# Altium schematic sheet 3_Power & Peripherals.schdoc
size 309 x 223 mm; Symbol: Artery_A4; Device: Artery_A4; Company: Artery Technology; Drawed: SD; Version: 1.0; Page Size: A4; @Project Name: AT-START-F490; @Page Count: 4; @Update Date: 2024-11-26; @Create Date: 2024-11-26; @Schematic Name: AT-START-F490; @Page No: 3; @Page Name: Power & Peripherals; @Board Name: AT-START-F490 V1.0; @Create Time: 14:05:45; @Update Time: 14:06:00
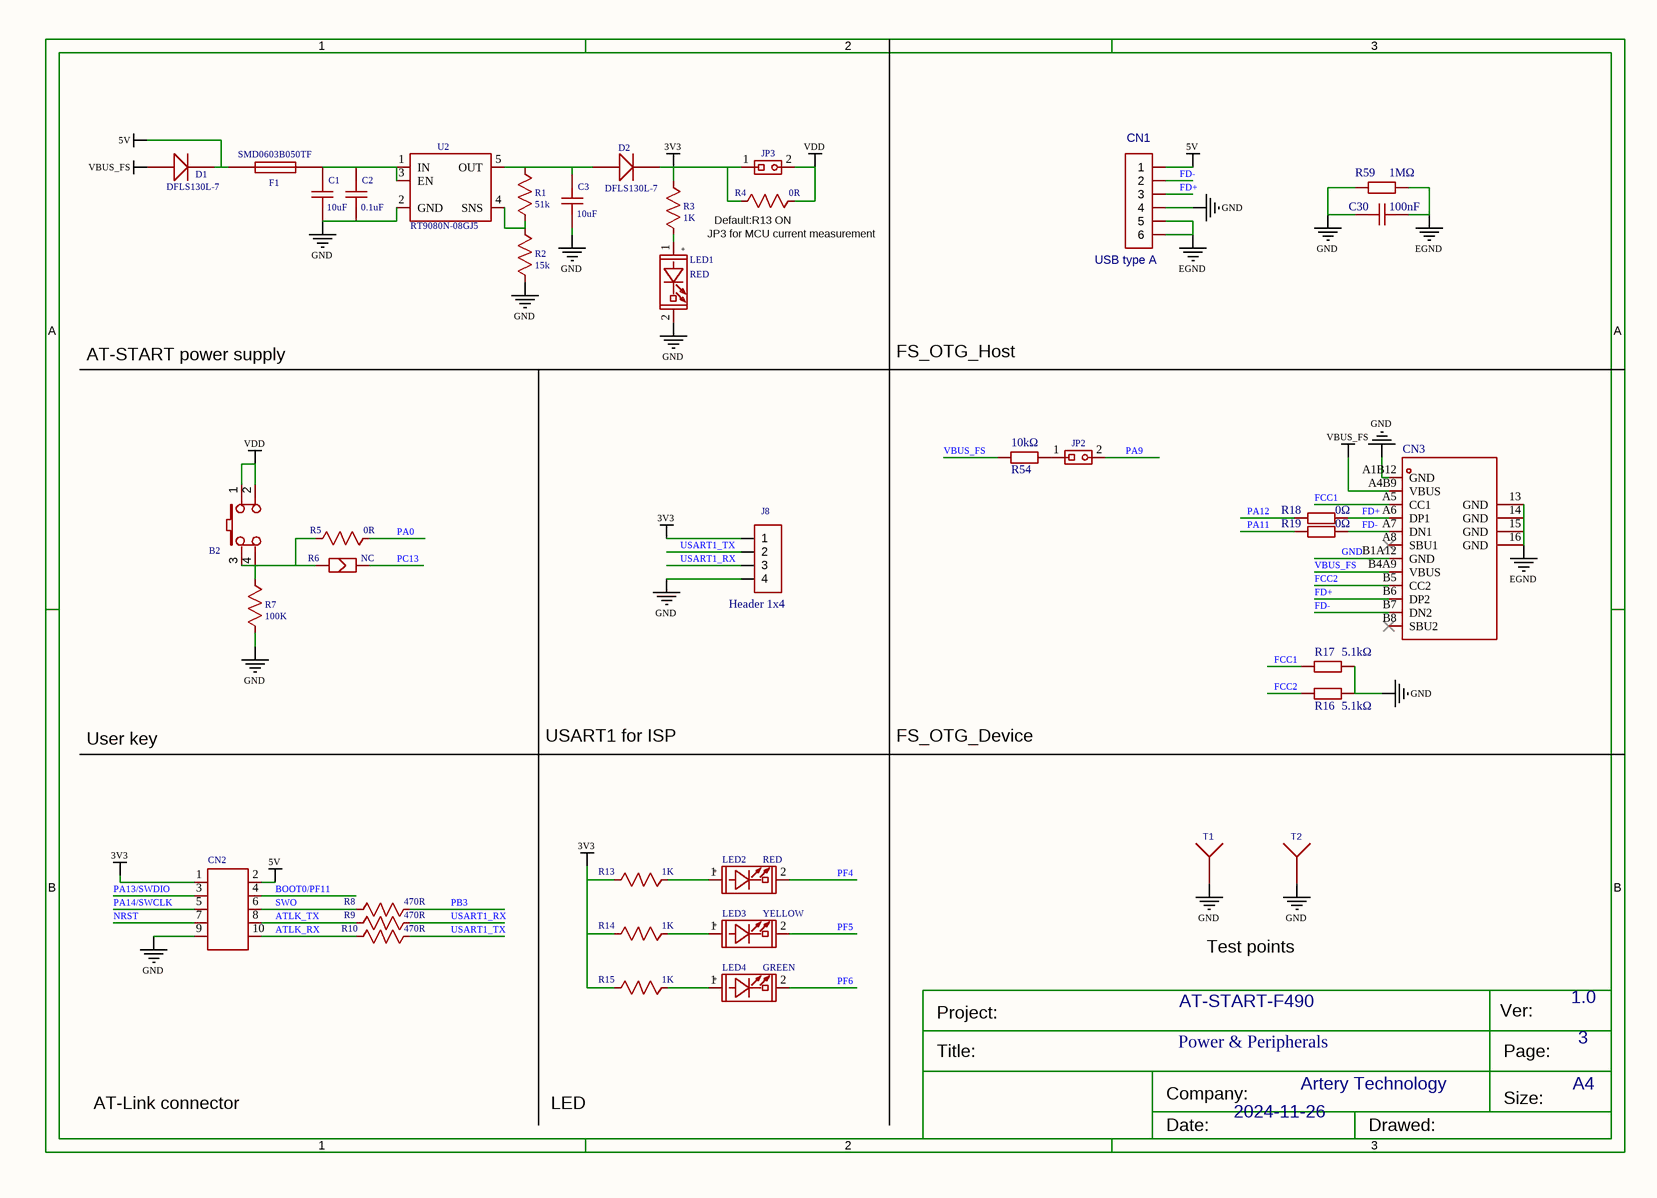
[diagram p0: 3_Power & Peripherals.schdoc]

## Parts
B2  BUTTON_SMT,6.0x6.0x4.5mm  [BUTTON_SMT_6*6*5]  (value not drawn)
C1  10uF  [0603_C-M]
C2  0.1uF  [0603_C-M]
C3  10uF  [0603_C-M]
C30  value 100nF  [C0603]
CN1  USB type A  [USB-A-TH__USB-AF-90]
CN2  NC(Header 2x5)  [HDR2X5]  (value not drawn)
CN3  (no value)  [USB-C-SMD_TYPEC-304-BCP16]
D1  DFLS130L-7  [SOD-123]
D2  DFLS130L-7  [SOD-123]
F1  SMD0603B050TF  [R0603]
J8  Header 1x4  [HDR1X4]
JP2  NC(Header 1x2)  [HEADER 1X2]  (value not drawn)
JP3  NC(Header 1x2)  [HEADER 1X2]  (value not drawn)
LED1  RED  [LED0603]
LED2  RED  [LED0603]
LED3  YELLOW  [LED0603]
LED4  GREEN  [LED0603]
R1  51k  [0603_R-M]
R2  15k  [0603_R-M]
R3  1K  [0603_R-M]
R4  0R  [0603_R-M]
R5  0R  [0603_R-M]
R6  NC  [SB-PAD]
R7  100K  [0603_R-M]
R8  470R  [0603_R-M]
R9  470R  [0603_R-M]
R10  470R  [0603_R-M]
R13  1K  [0603_R-M]
R14  1K  [0603_R-M]
R15  1K  [0603_R-M]
R16  value 5.1kΩ  [R0603]
R17  value 5.1kΩ  [R0603]
R18  0Ω  [R0603]
R19  0Ω  [R0603]
R54  value 10kΩ  [R0603]
R59  value 1MΩ  [R0603]
T1  Testpoint  [TESTHOOK]  (value not drawn)
T2  Testpoint  [TESTHOOK]  (value not drawn)
U2  RT9080N-08GJ5  [SOT-23-5]

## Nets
3V3: CN2.1 D2.2(K) J8.1 JP3.1 R3.1 R4.2 R13.2 R14.2 R15.2
5V: CN1.1 CN2.2 D1.2(K) F1.1
EGND: C30.2 CN1.SH1(5) CN1.SH2(6) CN3.13(GND) CN3.14(GND) CN3.15(GND) CN3.16(GND) R59.1
GND: C1.2 C2.2 C3.2 C30.1 CN1.4 CN2.9 CN3.A1B12(GND) CN3.B1A12(GND) J8.4 LED1.2(CATHODE) R2.1 R7.2 R16.2 R17.2 R59.2 T1.1 T2.1 U2.2(GND)
VBUS_FS: CN3.A4B9(VBUS) CN3.B4A9(VBUS) D1.1(A) R54.2
VDD: B2.1 B2.2 JP3.2 R4.1
ATLK_RX: CN2.10 R10.2
ATLK_TX: CN2.8 R9.2
BOOT0/PF11: CN2.4
FCC1: CN3.A5(CC1) R17.1
FCC2: CN3.B5(CC2) R16.1
FD+: CN1.3 CN3.A6(DP1) CN3.B6(DP2) R18.2
FD-: CN1.2 CN3.A7(DN1) CN3.B7(DN2) R19.2
NRST: CN2.7
PA0: R5.1
PA9: JP2.2
PA11: R19.1
PA12: R18.1
PA13/SWDIO: CN2.3
PA14/SWCLK: CN2.5
PB3: R8.1
PC13: R6.2
PF4: LED2.2(CATHODE)
PF5: LED3.2(CATHODE)
PF6: LED4.2(CATHODE)
SWO: CN2.6 R8.2
USART1_RX: J8.3 R9.1
USART1_TX: J8.2 R10.1
NetB2_3: B2.3 B2.4 R5.2 R6.1 R7.1
NetC1_1: C1.1 C2.1 F1.2 U2.1(IN) U2.3(EN)
NetC3_1: C3.1 D2.1(A) R1.2 U2.5(OUT)
NetJP2_1: JP2.1 R54.1
NetLED1_1: LED1.1(ANODE) R3.2
NetLED2_1: LED2.1(ANODE) R13.1
NetLED3_1: LED3.1(ANODE) R14.1
NetLED4_1: LED4.1(ANODE) R15.1
NetR1_1: R1.1 R2.2 U2.4(SNS)

Not connected (* = marked no-connect by the designer): CN3 A8(SBU1)* B8(SBU2)*

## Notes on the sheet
- JP3 for MCU current measurement
- (near R4) Default:R13 ON
- AT-START power supply
- FS_OTG_Host
- User key
- USART1 for ISP
- FS_OTG_Device
- Test points
- AT-Link connector
- LED

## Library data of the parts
B2 = BUTTON_SMT,6.0x6.0x4.5mm: Convert to PCB: yes
C1 C3 = 10uF: Convert to PCB: yes
C2 = 0.1uF: Convert to PCB: yes
C30 = CC0603KRX7R9BB104: Manufacturer: YAGEO(国巨); Add into BOM: yes; Tolerance: ±10%; Voltage Rated: 50V; Temperature Coefficient: X7R
CN1 = USB type A: Convert to PCB: yes
CN2 = NC(Header 2x5): Convert to PCB: yes
CN3 = TYPEC-304-BCP16: Manufacturer: XUNPU(讯普); Add into BOM: yes; Connector Type: Type-C; Gender: 母座; Number of Contacts: 16.0; Number of Ports: 1; Mounting Sytle: 卧贴; Current Rating - Power (Max): 3A; Welding Temperature (Max): 260
D1 D2 = DFLS130L-7: Convert to PCB: yes
F1 = SMD0603B050TF: Convert to PCB: yes
J8 = Header 1x4: Convert to PCB: yes
JP2 JP3 = NC(Header 1x2): Convert to PCB: yes
LED1 LED2 = RED: Convert to PCB: yes
LED3 = YELLOW: Convert to PCB: yes
LED4 = GREEN: Convert to PCB: yes
R1 = 51k: Convert to PCB: yes
R2 = 15k: Convert to PCB: yes
R3 R13-R15 = 1K: Convert to PCB: yes
R4 R5 = 0R: Convert to PCB: yes
R6 = NC: Convert to PCB: yes
R7 = 100K: Convert to PCB: yes
R8-R10 = 470R: Convert to PCB: yes
R16 R17 = 0603WAF5101T5E: Manufacturer: UNI-ROYAL(厚声); Add into BOM: yes; Tolerance: ±1%; Power(Watts): 1/10W; Temperature Coefficient: ±100ppm/; Overload Voltage (Max): 75V
R18 R19 = 0603WAF220JT5E: Manufacturer: UNI-ROYAL(厚声); Add into BOM: yes; Tolerance: ±1%; Power(Watts): 100mW; Temperature Coefficient: ±100ppm/; Overload Voltage (Max): 75V
R54 = 0603WAF1002T5E: Manufacturer: UNI-ROYAL(厚声); Add into BOM: yes; Tolerance: ±1%; Power(Watts): 1/10W; Temperature Coefficient: ±100ppm/; Overload Voltage (Max): 75V
R59 = RC0603FR-071ML: Manufacturer: YAGEO(国巨); Add into BOM: yes; Tolerance: ±1%; Power(Watts): 100mW; Temperature Coefficient: ±100ppm/; Overload Voltage (Max): 75V
T1 T2 = Testpoint: Convert to PCB: yes
U2 = RT9080N-08GJ5: Convert to PCB: yes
